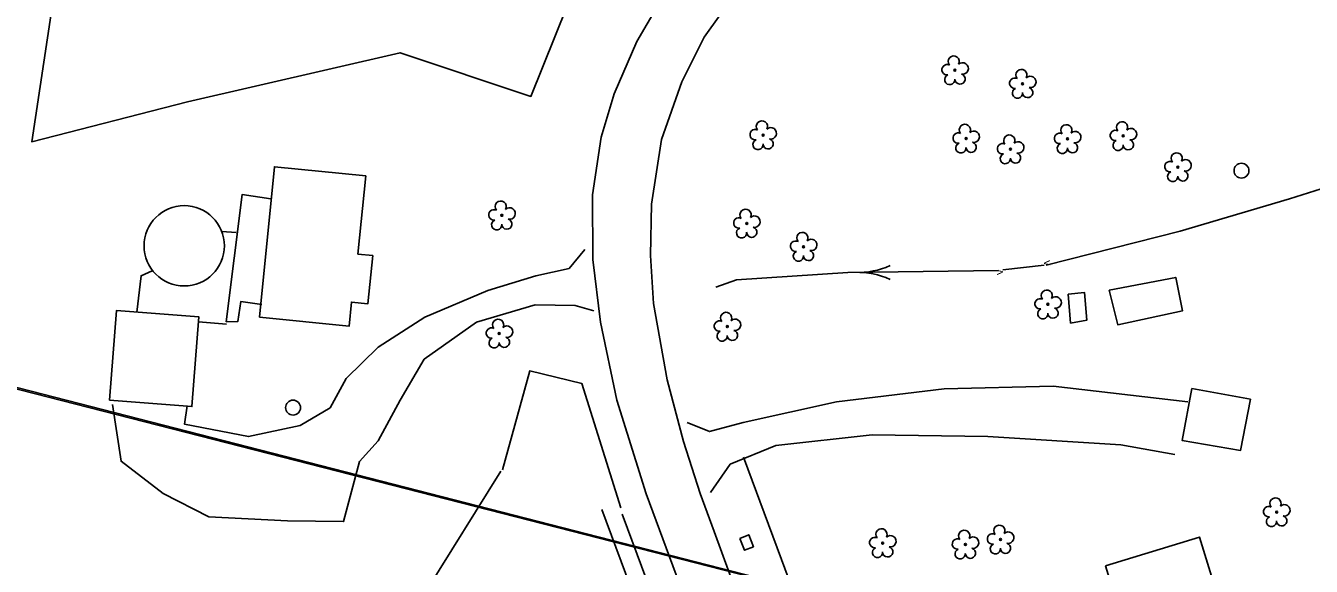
# Model space of a CAD drawing. Extents: x 1380524 to 1382335, y 594765 to 596944.
# Drawn here: x 1381565.9 to 1381991.4, y 596039.1 to 596218 of the extents above; entities that cross this region are included whole.
import ezdxf

# ---------------------------------------------------------------- set-up
doc = ezdxf.new("R2010")
doc.units = 0
for name, color, linetype in [('DTM Contours Major Text', 7, 'Continuous'), ('DTM Contours Minor Text', 7, 'Continuous'), ('Exist Roads EOP', 7, 'Continuous'), ('Prop Drainage Ditch Base Lines', 7, 'Continuous'), ('Prop Drainage Ditch Flow Line', 7, 'Continuous'), ('Prop Drainage Structure Box Number Symbol CELL', 7, 'Continuous'), ('Prop Drainage Structure Drop Inlet Grate 2 Narrow Slots and Flat Grates 840 29 CELL', 7, 'Continuous'), ('Prop Drainage Structure Pipe Elbow CELL', 7, 'Continuous'), ('Prop Drainage Structure Pipe Elbow Label', 7, 'Continuous'), ('Prop Drainage Structure Plot Symbol 20 Scale CELL', 7, 'Continuous'), ('Prop Drainage Structure Plot Symbol 50 Scale CELL', 7, 'Continuous'), ('Prop Earthen Structure Cut Ditch Special Detail Label', 7, 'Continuous'), ('Prop Earthen Structure Ditch Flow Line', 7, 'Continuous'), ('Prop Erosion Rip Rap At Embankment Detail CELL', 7, 'Continuous')]:
    doc.layers.add(name, color=color, linetype=linetype)

# ---------------------------------------------------------------- blocks, each defined once
blk = doc.blocks.new('EXIST HYDRO STREAM FLOW ARROW')
at = {"layer": 'DTM Contours Minor Text'}
blk.add_line((0, 0), (0, 0), dxfattribs=at)
for points in [[(-0.1, 0.04575), (-0.07325, 0.03375), (-0.04475, 0.0245), (-0.0165, 0.01575), (0.01175, 0.0095), (0.041, 0.00475), (0.07075, 0.0015), (0.1, 0)], [(-0.1, -0.04575), (-0.07325, -0.03375), (-0.04475, -0.0245), (-0.0165, -0.01575), (0.01175, -0.0095), (0.041, -0.00475), (0.07075, -0.0015), (0.1, 0)]]:
    blk.add_lwpolyline(points, dxfattribs=at)
blk = doc.blocks.new('EXIST UTILITIES OTHER POLE')
at = {"layer": 'DTM Contours Major Text'}
blk.add_circle((0, 0), 0.0493, dxfattribs=at)
blk = doc.blocks.new('EXIST VEGETATION TREE')
at = {"layer": 'Prop Erosion Rip Rap At Embankment Detail CELL'}
blk.add_line((0, 0), (0, 0), dxfattribs=at)
blk.add_circle((0, 0), 0.00652, dxfattribs=at)
for centre, radius, start, end in [((-0.0077, 0.0575), 0.0371, 330.16508, 219.71335), ((-0.0521, 0.0031), 0.0345, 62.66361, 279.3457), ((0.051, 0.0118), 0.038, 257.1011, 134.19993), ((-0.0341, -0.0624), 0.0338, 111.56708, 6.23104), ((0.0335, -0.058), 0.034, 181.28216, 74.55999)]:
    blk.add_arc(centre, radius, start, end, dxfattribs=at)

msp = doc.modelspace()

# ---------------------------------------------------------------- linework, layer by layer
at = {"layer": 'Exist Roads EOP'}
for points in [[(1381803.49, 596075.21), (1381839.46, 595978.27), (1381864.07, 595917.48)], [(1381756.61, 596057.82), (1381792.83, 595960.19), (1381822.94, 595885.83), (1381838.07, 595842.58)]]:
    msp.add_lwpolyline(points, dxfattribs=at)
at = {"layer": 'Prop Drainage Ditch Base Lines'}
for points in [[(1381643.25, 596121.48), (1381648.21, 596171.29), (1381678.41, 596168.28), (1381675.83, 596142.38), (1381680.73, 596141.89), (1381679.14, 596125.98), (1381673.71, 596126.52), (1381672.91, 596118.52)], [(1381924.46, 596130.47), (1381946.56, 596134.66), (1381948.84, 596123.66), (1381927.35, 596118.98)], [(1381910.9, 596129.12), (1381911.74, 596119.56), (1381917.14, 596120.54), (1381916.37, 596129.67)], [(1381593.6, 596094.05), (1381595.89, 596123.7), (1381623.21, 596121.6), (1381620.92, 596091.94)], [(1381951.93, 596097.95), (1381971.29, 596094.36), (1381968.01, 596077.43), (1381948.64, 596080.73)], [(1381923.31, 596039.17), (1381945.14, 595968.12), (1381976.25, 595977.68), (1381954.42, 596048.73)]]:
    msp.add_lwpolyline(points, close=True, dxfattribs=at)
at = {"layer": 'Prop Drainage Ditch Flow Line'}
msp.add_lwpolyline([(1381802.24, 596048.3), (1381805.19, 596049.48), (1381806.76, 596045.55), (1381803.81, 596044.36)], close=True, dxfattribs=at)
at = {"layer": 'Prop Drainage Structure Box Number Symbol CELL'}
for points in [[(1382083.99, 595964.39), (1380966.64, 596251.47), (1381106.82, 596554.99), (1381897.61, 596920.15), (1382148.43, 596473.2)], [(1382083.62, 595964.41), (1382120.69, 595773.82), (1382095.82, 595646.75), (1382010.85, 595488.75), (1381848.52, 595352.32), (1381617.36, 595239.15), (1381304.92, 595184.07), (1381005.77, 595330.75), (1380937.13, 595525.19), (1380768.47, 595849.39), (1380967, 596250.36)]]:
    msp.add_lwpolyline(points, close=True, dxfattribs=at)
at = {"layer": 'Prop Drainage Structure Drop Inlet Grate 2 Narrow Slots and Flat Grates 840 29 CELL'}
msp.add_circle((1381618.35, 596145.13), 13.29, dxfattribs=at)
at = {"layer": 'Prop Drainage Structure Pipe Elbow CELL'}
for points in [[(1381656.75, 596085.62), (1381666.63, 596091.51), (1381671.96, 596101.17), (1381682.53, 596111.61), (1381698.03, 596121.53), (1381718.8, 596130.29), (1381734.69, 596135.19), (1381745.72, 596137.58), (1381750.97, 596143.88)], [(1381753.97, 596123.66), (1381747.77, 596125.39), (1381734.53, 596125.58), (1381715.1, 596119.81), (1381697.79, 596107.58), (1381689.78, 596094.1), (1381682.5, 596080.64)], [(1381950.56, 596093.46), (1381906.03, 596098.69), (1381869.95, 596097.84), (1381834.25, 596093.49), (1381803.41, 596086.66), (1381792.21, 596083.65), (1381784.85, 596086.61)], [(1381594.59, 596092.61), (1381597.46, 596073.85), (1381611.42, 596063.15), (1381626.46, 596055.41), (1381652.51, 596054.06), (1381671.12, 596053.85), (1381676.33, 596073.73), (1381682.5, 596080.64)], [(1381656.75, 596085.62), (1381639.64, 596082.02), (1381618.45, 596086.08), (1381619.27, 596092.18)], [(1381792.53, 596063.51), (1381799.11, 596072.85), (1381814.22, 596079.02), (1381846.02, 596082.54), (1381884.35, 596082.07), (1381928.33, 596079.28), (1381946.27, 596076.1)]]:
    msp.add_lwpolyline(points, dxfattribs=at)
at = {"layer": 'Prop Drainage Structure Pipe Elbow Label'}
msp.add_lwpolyline([(1381889.28, 596137.15), (1381903.01, 596138.7)], dxfattribs=at)
at = {"layer": 'Prop Drainage Structure Plot Symbol 20 Scale CELL'}
for points in [[(1381903.65, 596138.7), (1381948.03, 596149.99), (1381984.23, 596160.72), (1382013.51, 596169.97), (1382032.7, 596177.77), (1382059.4, 596189.79), (1382079.06, 596191.47), (1382091.96, 596186.73)], [(1381794.33, 596131.39), (1381801.12, 596133.84), (1381838, 596136.27), (1381887.92, 596136.94)]]:
    msp.add_lwpolyline(points, dxfattribs=at)
at = {"layer": 'Prop Drainage Structure Plot Symbol 50 Scale CELL'}
for p, q in [((1381630.79, 596149.85), (1381635.52, 596149.54)), ((1381623.11, 596119.94), (1381632.36, 596119.15))]:
    msp.add_line(p, q, dxfattribs=at)
for points in [[(1381647.05, 596160.67), (1381637.49, 596162.08), (1381632.27, 596119.98), (1381636.07, 596120.05), (1381637.14, 596126.74), (1381644.01, 596125.67)], [(1381602.71, 596123.13), (1381604.06, 596135.21), (1381607.72, 596136.87)]]:
    msp.add_lwpolyline(points, dxfattribs=at)
at = {"layer": 'Prop Earthen Structure Cut Ditch Special Detail Label'}
for points in [[(1381993.97, 596746.39), (1381926.82, 596678.09), (1381882.73, 596673.31), (1381857.71, 596563.06), (1381849.31, 596464.5), (1381837.19, 596379.89), (1381830.78, 596342.77), (1381810.83, 596299.24), (1381745.1, 596224.39), (1381733.09, 596194.6), (1381689.78, 596209.04), (1381619.47, 596192.74), (1381567.86, 596179.57), (1381583.81, 596285.11), (1381565.74, 596343.12), (1381520.02, 596437.2), (1381483.63, 596516.56), (1381436.21, 596610.27), (1381402.81, 596651.16), (1381345.44, 596643.18), (1381336.65, 596668.79)], [(1381723.75, 596071.03), (1381732.73, 596103.71), (1381749.97, 596099.51), (1381762.85, 596058.46)], [(1381763.26, 596056.35), (1381789.24, 595986.58), (1381768.13, 595997.86), (1381730.48, 595989.33), (1381698.5, 596031.05), (1381723.1, 596070.54)]]:
    msp.add_lwpolyline(points, dxfattribs=at)
at = {"layer": 'Prop Earthen Structure Ditch Flow Line'}
for points in [[(1381771.25, 596063.05), (1381761.55, 596094.09), (1381756.1, 596119.83), (1381753.59, 596140.63), (1381753.54, 596162.01), (1381756.32, 596181.14), (1381760.61, 596195.42), (1381768.2, 596212.74), (1381777.61, 596229.03)], [(1381800.53, 596228.26), (1381790.43, 596214.19), (1381783.06, 596199.4), (1381776.36, 596180.31), (1381772.99, 596158.9), (1381772.72, 596141.92), (1381773.72, 596126.09), (1381778.2, 596100.78), (1381783.63, 596080.38), (1381789.17, 596063.13)], [(1381771.25, 596063.05), (1381807.38, 595965.66), (1381837.55, 595891.15), (1381853.43, 595845.6)], [(1382091.45, 595950.01), (1382040.09, 595937.29), (1382004.26, 595928.01), (1381958.8, 595916.53), (1381926.33, 595908.18), (1381894.21, 595900.91), (1381876.52, 595897.14), (1381867, 595896.29), (1381860.37, 595897.28), (1381854.86, 595900.27), (1381851.95, 595903.63), (1381839.95, 595931.67), (1381826.08, 595965.16), (1381814.38, 595994.56), (1381803.44, 596023.95), (1381793.75, 596050.62), (1381789.17, 596063.13)]]:
    msp.add_lwpolyline(points, dxfattribs=at)

# ---------------------------------------------------------------- block references
at = {"layer": 'DTM Contours Major Text', "xscale": 50, "yscale": 50}
for p in [(1381968.31, 596170.01), (1381654.38, 596091.58)]:
    msp.add_blockref('EXIST UTILITIES OTHER POLE', p, dxfattribs=at)
at = {"layer": 'DTM Contours Minor Text', "xscale": 50, "yscale": 50, "rotation": -179.99998055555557}
msp.add_blockref('EXIST HYDRO STREAM FLOW ARROW', (1381846.97, 596136.32), dxfattribs=at)
at = {"layer": 'Prop Erosion Rip Rap At Embankment Detail CELL', "xscale": 50, "yscale": 50}
for p in [(1381873.46, 596203.25), (1381895.86, 596198.78), (1381809.96, 596181.77), (1381877.14, 596180.64), (1381910.72, 596180.5), (1381929.18, 596181.49), (1381891.84, 596177.1), (1381947.25, 596171.17), (1381723.48, 596155.22), (1381804.54, 596152.53), (1381823.34, 596144.83), (1381904.24, 596125.77), (1381722.64, 596116.11), (1381798.12, 596118.4), (1381979.96, 596057), (1381979.96, 596057), (1381888.54, 596047.95), (1381849.54, 596046.75), (1381876.91, 596046.29)]:
    msp.add_blockref('EXIST VEGETATION TREE', p, dxfattribs=at)

# ---------------------------------------------------------------- texts
at = {"layer": 'Prop Drainage Structure Pipe Elbow Label'}
for rotation, p in [(276.7047, (1381902.84, 596140.19)), (96.223, (1381889.45, 596135.65))]:
    msp.add_text('v', height=2.65, rotation=rotation, dxfattribs=at).set_placement(p)

doc.saveas('drawing.dxf')
